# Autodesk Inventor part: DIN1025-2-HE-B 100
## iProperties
Created: 2006-03
Part Number: DIN1025-2-HE-B 100
Material: S 235 JRG2
Document SubType Name: Modeling
Designer: rgl
Density: 7.85 g/cm^3
Abmessung: DIN1025-2-HE-B 100 ...100 lg
DIN/ASME: EN 10 025
Author: rgl
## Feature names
1. Extrusion1
2. Rundung1 [Fillet]
